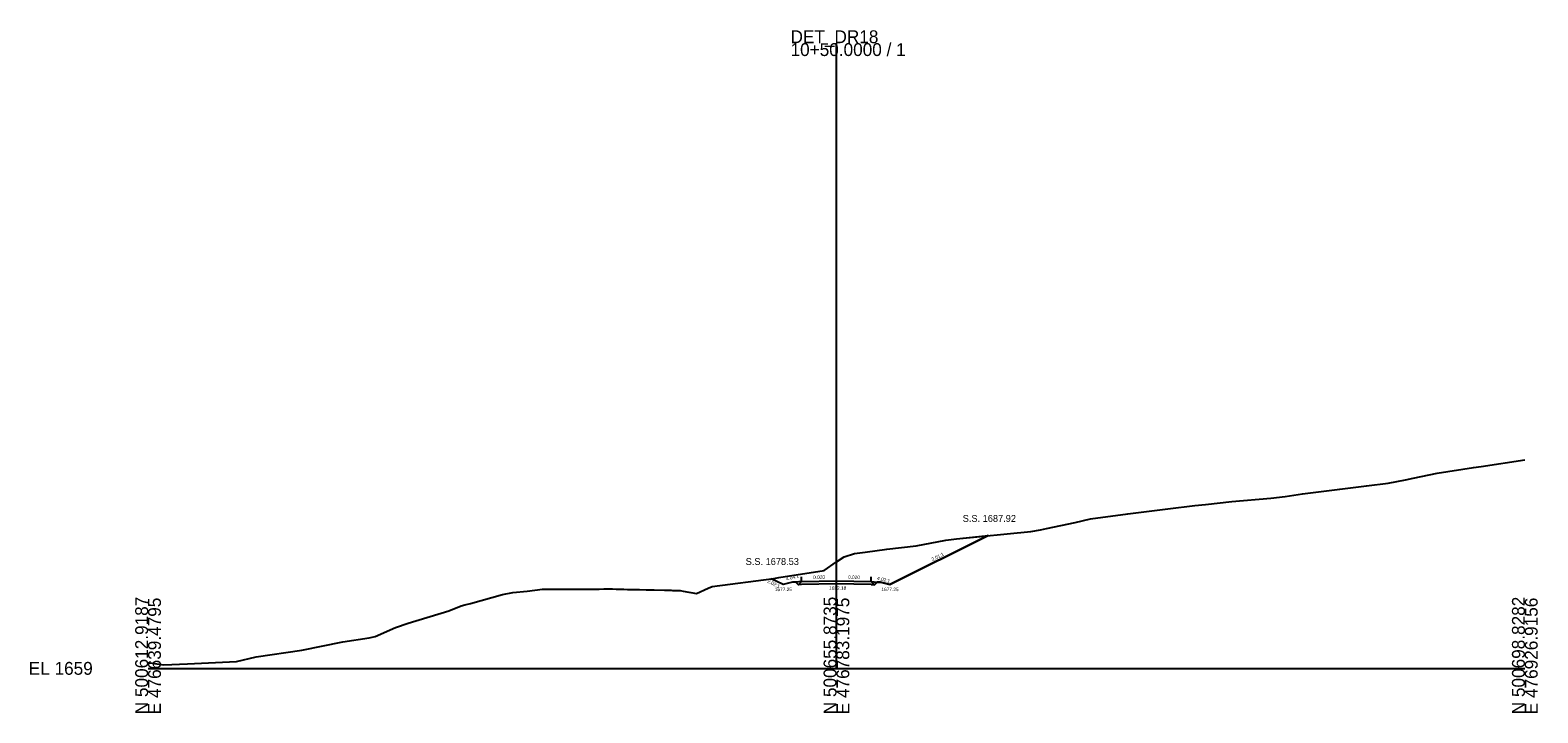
# Model space of a CAD drawing. Extents: x -26 to 303, y -10 to 3627.
# Drawn here: x -25.7 to 302.8, y 990.3 to 1139.1 of the extents above; entities that cross this region are included whole.
import ezdxf

# ---------------------------------------------------------------- set-up
doc = ezdxf.new("R2010")
doc.units = 0
for name, color, linetype in [('Exist Cross Section Cell', 7, 'Continuous'), ('Exist XS Center Line Elevation Label', 7, 'Continuous'), ('Exist XS Ground Line', 7, 'Continuous'), ('Prop XS Ditch Slope Text', 7, 'Continuous'), ('Prop XS Ditch Standard Text', 7, 'Continuous'), ('Prop XS Dump Level', 7, 'Continuous'), ('Prop XS Earthwork Shape', 7, 'Continuous'), ('Prop XS EOT Tick Mark', 7, 'Continuous'), ('Prop XS Finish Grade', 7, 'Continuous'), ('Prop XS Finish Grade Earthwork', 7, 'Continuous'), ('Prop XS Finish Grade Pavement', 7, 'Continuous'), ('Prop XS Hydro Typical Ditch Data', 7, 'Continuous'), ('Prop XS Pvmt Edge Slope', 7, 'Continuous'), ('Prop XS SE Text', 7, 'Continuous'), ('Prop XS Shoulder Borrow Shape', 7, 'Continuous'), ('Prop XS Side Slope Text', 7, 'Continuous'), ('Prop XS SS Elevation Text', 7, 'Continuous'), ('Prop XS Subgrade Earthwork', 7, 'Continuous')]:
    doc.layers.add(name, color=color, linetype=linetype)

msp = doc.modelspace()

# ---------------------------------------------------------------- linework, layer by layer
at = {"layer": 'Exist Cross Section Cell'}
for p, q in [((150, 1000), (150, 1136.23)), ((0, 1000), (150, 1000)), ((150, 1000), (300, 1000))]:
    msp.add_line(p, q, dxfattribs=at)
at = {"layer": 'Exist XS Ground Line'}
msp.add_lwpolyline([(0, 1001.23), (0.53, 1001.17), (1.42, 1001.05), (3.45, 1000.78), (8.56, 1000.97), (19.3, 1001.5), (23.58, 1002.5), (33.52, 1004), (42.43, 1005.77), (48.17, 1006.66), (49.51, 1006.97), (53.95, 1008.87), (56.68, 1009.82), (65.51, 1012.55), (68.24, 1013.59), (68.99, 1013.81), (70.25, 1014.15), (77.24, 1016.12), (79.5, 1016.51), (82.64, 1016.81), (85.96, 1017.24), (86.62, 1017.23), (88.14, 1017.24), (88.84, 1017.24), (89.88, 1017.25), (91.46, 1017.24), (92.24, 1017.25), (94.35, 1017.27), (95.26, 1017.28), (96.67, 1017.28), (98.28, 1017.29), (99.28, 1017.3), (100, 1017.3), (101.18, 1017.31), (102.03, 1017.28), (103.7, 1017.24), (104.48, 1017.21), (106.37, 1017.17), (107.09, 1017.15), (108.54, 1017.12), (109.71, 1017.09), (110.3, 1017.08), (112.51, 1017.03), (113.97, 1017.01), (114.29, 1017), (114.75, 1016.99), (115.95, 1016.97), (116.62, 1016.82), (119.5, 1016.29), (122.07, 1017.47), (122.89, 1017.83), (136.34, 1019.61), (137.45, 1019.82), (147.31, 1021.34), (150, 1023.18), (151.66, 1024.32), (153.96, 1025), (156.24, 1025.3), (161, 1025.99), (167.39, 1026.72), (173.87, 1027.96), (176.16, 1028.23), (192.37, 1029.85), (194.46, 1030.19), (195.8, 1030.5), (202.01, 1031.75), (205.34, 1032.58), (213.49, 1033.7), (222.18, 1034.76), (228.1, 1035.48), (230.41, 1035.7), (236.16, 1036.34), (244.68, 1037.08), (247.8, 1037.44), (251.53, 1038.01), (259.66, 1039.04), (265.48, 1039.77), (270.25, 1040.35), (273.98, 1041.11), (275.68, 1041.42), (280.89, 1042.51), (288.82, 1043.79), (290.5, 1043.96), (300, 1045.41)], dxfattribs=at)
at = {"layer": 'Prop XS Dump Level'}
for p, q in [((142.42, 1018.91), (150, 1019.06)), ((150, 1019.06), (157.58, 1018.91))]:
    msp.add_line(p, q, dxfattribs=at)
at = {"layer": 'Prop XS Earthwork Shape'}
msp.add_lwpolyline([(150, 1018.4), (142.42, 1018.25), (141.73, 1018.23), (141.14, 1018.81), (140.4, 1018.75), (138.38, 1018.25), (135.79, 1019.53), (136.34, 1019.61), (137.45, 1019.82), (147.31, 1021.34), (150, 1023.18), (151.66, 1024.32), (153.96, 1025), (156.24, 1025.3), (161, 1025.99), (167.39, 1026.72), (173.87, 1027.96), (176.16, 1028.23), (183.06, 1028.92), (161.61, 1018.25), (159.59, 1018.75), (158.85, 1018.81), (158.27, 1018.23), (157.58, 1018.25)], close=True, dxfattribs=at)
at = {"layer": 'Prop XS EOT Tick Mark'}
for p, q in [((142.42, 1018.91), (142.42, 1019.91)), ((157.58, 1018.91), (157.58, 1019.91))]:
    msp.add_line(p, q, dxfattribs=at)
at = {"layer": 'Prop XS Finish Grade'}
for p, q in [((142.42, 1018.91), (141.14, 1018.81)), ((157.58, 1018.91), (158.85, 1018.81))]:
    msp.add_line(p, q, dxfattribs=at)
at = {"layer": 'Prop XS Finish Grade Earthwork'}
for p, q in [((161.61, 1018.25), (183.06, 1028.92)), ((138.38, 1018.25), (135.79, 1019.53)), ((140.4, 1018.75), (138.38, 1018.25)), ((141.14, 1018.81), (140.4, 1018.75)), ((158.85, 1018.81), (159.59, 1018.75)), ((159.59, 1018.75), (161.61, 1018.25))]:
    msp.add_line(p, q, dxfattribs=at)
at = {"layer": 'Prop XS Finish Grade Pavement'}
for p, q in [((142.42, 1018.91), (150, 1019.06)), ((150, 1019.06), (157.58, 1018.91))]:
    msp.add_line(p, q, dxfattribs=at)
at = {"layer": 'Prop XS Hydro Typical Ditch Data'}
for p, q in [((161.61, 1018.25), (183.06, 1028.92)), ((138.38, 1018.25), (135.79, 1019.53)), ((140.4, 1018.75), (138.38, 1018.25)), ((159.59, 1018.75), (161.61, 1018.25))]:
    msp.add_line(p, q, dxfattribs=at)
at = {"layer": 'Prop XS Pvmt Edge Slope'}
for p, q in [((142.42, 1018.91), (141.73, 1018.23)), ((157.58, 1018.91), (158.27, 1018.23))]:
    msp.add_line(p, q, dxfattribs=at)
at = {"layer": 'Prop XS Shoulder Borrow Shape'}
for points in [[(142.42, 1018.91), (141.14, 1018.81), (141.73, 1018.23)], [(142.42, 1018.91), (141.14, 1018.81), (141.73, 1018.23)], [(157.58, 1018.91), (158.85, 1018.81), (158.27, 1018.23)], [(157.58, 1018.91), (158.85, 1018.81), (158.27, 1018.23)]]:
    msp.add_lwpolyline(points, close=True, dxfattribs=at)
at = {"layer": 'Prop XS Subgrade Earthwork'}
for p, q in [((141.73, 1018.23), (141.14, 1018.81)), ((158.27, 1018.23), (158.85, 1018.81)), ((142.42, 1018.25), (141.73, 1018.23)), ((150, 1018.4), (142.42, 1018.25)), ((157.58, 1018.25), (150, 1018.4)), ((157.58, 1018.25), (158.27, 1018.23))]:
    msp.add_line(p, q, dxfattribs=at)

# ---------------------------------------------------------------- texts
at = {"layer": 'Exist Cross Section Cell'}
for s, p in [('DET_DR18', (140, 1136.23)), ('10+50.0000 / 1', (140, 1133.43)), ('EL 1659', (-26, 998.6))]:
    msp.add_text(s, height=2.8, dxfattribs=at).set_placement(p)
for s, p in [('N 500612.9187', (0, 990)), ('E 476639.4795', (2.8, 990)), ('N 500655.8735', (150, 990)), ('E 476783.1975', (152.8, 990)), ('N 500698.8282', (300, 990)), ('E 476926.9156', (302.8, 990))]:
    msp.add_text(s, height=2.8, rotation=90, dxfattribs=at).set_placement(p)
at = {"layer": 'Exist XS Center Line Elevation Label'}
msp.add_text('1682.18', height=0.75, dxfattribs=at).set_placement((148.39, 1017.12))
at = {"layer": 'Prop XS Ditch Slope Text'}
for s, rotation, p in [('4.04:1', 13.9035, (139.09, 1019.13)), ('4.02:1', 346.0366, (158.8, 1019.31))]:
    msp.add_text(s, height=0.75, rotation=rotation, dxfattribs=at).set_placement(p)
at = {"layer": 'Prop XS Ditch Standard Text'}
for p in [(136.57, 1016.83), (159.8, 1016.83)]:
    msp.add_text('1677.25', height=0.75, dxfattribs=at).set_placement(p)
at = {"layer": 'Prop XS Dump Level'}
for p in [(140.4, 1018.71), (159.59, 1018.71)]:
    msp.add_text('Case1', height=0.04, dxfattribs=at).set_placement(p)
at = {"layer": 'Prop XS SE Text'}
for rotation, p in [(1.1458, (144.93, 1019.46)), (358.8542, (152.52, 1019.51))]:
    msp.add_text('0.020', height=0.75, rotation=rotation, dxfattribs=at).set_placement(p)
at = {"layer": 'Prop XS Side Slope Text'}
for s, rotation, p in [('2.01:1', 26.4412, (170.94, 1023.33)), ('2.02:1', 333.6609, (134.86, 1018.74))]:
    msp.add_text(s, height=0.75, rotation=rotation, dxfattribs=at).set_placement(p)
at = {"layer": 'Prop XS SS Elevation Text'}
for s, p in [('S.S. 1687.92', (177.52, 1031.92)), ('S.S. 1678.53', (130.22, 1022.53))]:
    msp.add_text(s, height=1.5, dxfattribs=at).set_placement(p)

doc.saveas('drawing.dxf')
